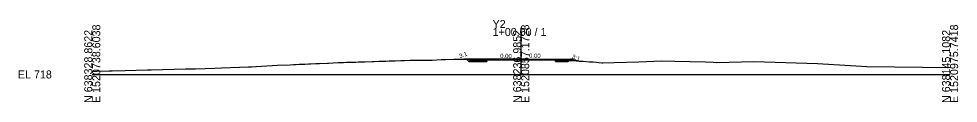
# Model space of a CAD drawing. Extents: x -26 to 1603, y -10 to 1019.
# Drawn here: x -25.7 to 302.8, y 990.3 to 1019.1 of the extents above; entities that cross this region are included whole.
import ezdxf

# ---------------------------------------------------------------- set-up
doc = ezdxf.new("R2010")
doc.units = 0
for name, color, linetype in [('Exist Cross Section Cell', 7, 'Continuous'), ('Exist XS Center Line Elevation Label', 7, 'Continuous'), ('Exist XS Ground Line', 7, 'Continuous'), ('Prop CMT Pvmt Course 1', 7, 'Continuous'), ('Prop CMT Pvmt Course 2', 7, 'Continuous'), ('Prop CMT Pvmt Course 3', 7, 'Continuous'), ('Prop CMT Pvmt Surface', 7, 'Continuous'), ('Prop CMT Slope Grass', 7, 'Continuous'), ('Prop CMT Subgrade Earthwork', 7, 'Continuous'), ('Prop XS Earthwork Shape', 7, 'Continuous')]:
    doc.layers.add(name, color=color, linetype=linetype)

msp = doc.modelspace()

# ---------------------------------------------------------------- linework, layer by layer
at = {"layer": 'Exist Cross Section Cell'}
for p, q in [((150, 1000), (150, 1016.27)), ((0, 1000), (150, 1000)), ((150, 1000), (300, 1000))]:
    msp.add_line(p, q, dxfattribs=at)
at = {"layer": 'Exist XS Ground Line'}
msp.add_lwpolyline([(0, 1001.03), (1.62, 1001.09), (5.91, 1001.23), (6.92, 1001.26), (11.56, 1001.38), (19.36, 1001.56), (19.96, 1001.57), (20.63, 1001.59), (32.57, 1001.91), (33.51, 1001.93), (34.62, 1001.97), (36.06, 1002.01), (42.84, 1002.24), (45.2, 1002.33), (54.65, 1002.66), (55.72, 1002.71), (57.31, 1002.78), (61.01, 1002.98), (64.75, 1003.2), (69.17, 1003.42), (70.37, 1003.47), (71.26, 1003.51), (72.4, 1003.57), (73.14, 1003.58), (73.56, 1003.59), (74.39, 1003.65), (75.67, 1003.7), (76.3, 1003.72), (78.17, 1003.8), (78.84, 1003.82), (79.46, 1003.85), (82.26, 1003.96), (82.62, 1003.98), (84.25, 1004.05), (86.03, 1004.13), (86.33, 1004.14), (87.81, 1004.21), (88.96, 1004.26), (89.6, 1004.27), (90.42, 1004.3), (92.12, 1004.35), (93.16, 1004.39), (94.5, 1004.42), (94.94, 1004.44), (95.28, 1004.45), (97.92, 1004.54), (98.59, 1004.56), (100.28, 1004.6), (101.59, 1004.65), (102.06, 1004.67), (102.68, 1004.68), (103.84, 1004.72), (104.96, 1004.76), (105.94, 1004.8), (107.9, 1004.86), (109.17, 1004.89), (111.06, 1004.95), (111.42, 1004.97), (113.44, 1005.02), (114.62, 1005.03), (115.74, 1005.03), (118.92, 1005.04), (122.02, 1005.22), (123.49, 1005.25), (126.45, 1005.3), (127.02, 1005.3), (127.69, 1005.31), (131.47, 1005.37), (132.17, 1005.39), (133.47, 1005.4), (135.36, 1005.4), (136.41, 1005.4), (137.11, 1005.4), (138.24, 1005.41), (139.58, 1005.4), (141.28, 1005.42), (142.73, 1005.42), (143.07, 1005.42), (143.48, 1005.41), (145.86, 1005.4), (147.55, 1005.4), (148.37, 1005.4), (149, 1005.4), (150.01, 1005.41), (150.45, 1005.42), (151.12, 1005.4), (151.86, 1005.38), (152.19, 1005.37), (154.1, 1005.34), (155.35, 1005.31), (155.71, 1005.31), (157.29, 1005.28), (158.5, 1005.26), (159.81, 1005.23), (161.45, 1005.19), (162.62, 1005.16), (164.29, 1005.06), (169.36, 1004.73), (170.24, 1004.68), (171.67, 1004.6), (173.85, 1004.47), (175.16, 1004.37), (178.2, 1004.11), (178.61, 1004.09), (182.43, 1004.2), (191.09, 1004.44), (199.06, 1004.77), (203.7, 1004.69), (214.48, 1004.37), (217.09, 1004.28), (218.45, 1004.24), (231.4, 1004.5), (253.61, 1003.79), (270.91, 1002.82), (300, 1002.38)], dxfattribs=at)
at = {"layer": 'Prop CMT Pvmt Course 1'}
msp.add_line((132.5, 1005.4), (165.62, 1005.4), dxfattribs=at)
at = {"layer": 'Prop CMT Pvmt Course 2'}
for p, q in [((138, 1005.4), (138, 1004.57)), ((162, 1004.57), (162, 1005.4)), ((132.25, 1005.15), (165.87, 1005.15))]:
    msp.add_line(p, q, dxfattribs=at)
at = {"layer": 'Prop CMT Pvmt Course 3'}
for p, q in [((131.92, 1004.82), (138, 1004.82)), ((162, 1004.82), (166.2, 1004.82))]:
    msp.add_line(p, q, dxfattribs=at)
at = {"layer": 'Prop CMT Pvmt Surface'}
msp.add_line((132.5, 1005.4), (165.62, 1005.4), dxfattribs=at)
at = {"layer": 'Prop CMT Slope Grass'}
for p, q in [((129.92, 1005.35), (130.5, 1005.33)), ((132.5, 1005.4), (130.5, 1005.33)), ((165.62, 1005.4), (167.62, 1005.33)), ((167.62, 1005.33), (169.41, 1004.73))]:
    msp.add_line(p, q, dxfattribs=at)
at = {"layer": 'Prop CMT Subgrade Earthwork'}
for p, q in [((131.67, 1004.57), (130.9, 1005.34)), ((132.5, 1005.4), (131.67, 1004.57)), ((165.62, 1005.4), (166.45, 1004.57)), ((166.45, 1004.57), (167.22, 1005.34)), ((131.67, 1004.57), (138, 1004.57)), ((138, 1004.57), (138, 1005.15)), ((138, 1005.15), (162, 1005.15)), ((162, 1005.15), (162, 1004.57)), ((162, 1004.57), (166.45, 1004.57))]:
    msp.add_line(p, q, dxfattribs=at)
at = {"layer": 'Prop XS Earthwork Shape'}
for points in [[(129.92, 1005.35), (131.47, 1005.37), (132.17, 1005.39), (132.5, 1005.4), (130.9, 1005.34), (130.5, 1005.33)], [(132.5, 1005.4), (130.9, 1005.34), (131.67, 1004.57)], [(151.29, 1005.4), (151.86, 1005.38), (152.19, 1005.37), (154.1, 1005.34), (155.35, 1005.31), (155.71, 1005.31), (157.29, 1005.28), (158.5, 1005.26), (159.81, 1005.23), (161.45, 1005.19), (162.62, 1005.16), (164.29, 1005.06), (166.07, 1004.94), (166.45, 1004.57), (162, 1004.57), (162, 1005.15), (138, 1005.15), (138, 1004.57), (131.67, 1004.57), (132.5, 1005.4)], [(132.5, 1005.4), (133.47, 1005.4), (135.36, 1005.4), (136.41, 1005.4), (137.11, 1005.4), (138.24, 1005.41), (139.58, 1005.4), (141.28, 1005.42), (142.73, 1005.42), (143.07, 1005.42), (143.48, 1005.41), (145.86, 1005.4), (147.55, 1005.4), (148.37, 1005.4), (149, 1005.4), (150.01, 1005.41), (150.45, 1005.42), (151.12, 1005.4), (151.29, 1005.4)], [(166.78, 1004.9), (169.36, 1004.73), (169.41, 1004.73), (167.62, 1005.33), (167.22, 1005.34)], [(166.07, 1004.94), (166.78, 1004.9), (166.45, 1004.57)]]:
    msp.add_lwpolyline(points, close=True, dxfattribs=at)

# ---------------------------------------------------------------- texts
at = {"layer": 'Exist Cross Section Cell'}
for s, p in [('Y2', (140, 1016.27)), ('1+00.00 / 1', (140, 1013.47)), ('EL 718', (-26, 998.6))]:
    msp.add_text(s, height=2.8, dxfattribs=at).set_placement(p)
for s, p in [('N 638328.8622', (0, 990)), ('E 1520738.6038', (2.8, 990)), ('N 638236.9852', (150, 990)), ('E 1520857.1728', (152.8, 990)), ('N 638145.1082', (300, 990)), ('E 1520975.7418', (302.8, 990))]:
    msp.add_text(s, height=2.8, rotation=90, dxfattribs=at).set_placement(p)
at = {"layer": 'Exist XS Center Line Elevation Label'}
for s, rotation, p in [('3:1', 19.8357, (128.59, 1005.64)), ('0.00', 358.8358, (142.65, 1005.77)), ('0.00', 358.8358, (152.76, 1005.84)), ('3:1', 340.1643, (167.59, 1005.65))]:
    msp.add_text(s, height=1.5, rotation=rotation, dxfattribs=at).set_placement(p)

doc.saveas('drawing.dxf')
